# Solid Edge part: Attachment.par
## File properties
Username: m_hel
Author: m_hel
Template: Iso Metric Part.par
Last saved by: m_hel
Revision: 8
Application: Solid Edge
Accuracy: 0,990
Material: Chrome
Face Style: Chrome
Fill Style: Normal
Virtual Style: Normal
Grouping: Uncategorized
LibraryName: Custom Materials
Coef. of Thermal Exp: 0.0
Thermal Conductivity: 0.0
Specific Heat: 0.0
Modulus of Elasticity: 0.0
Poisson's Ratio: 0.0
Yield Stress: 0.0
Ultimate Stress: 0.0
Elongation: 0.0
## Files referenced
..\..\Redfisher18.asm
G:\OneDriveTemp\OneDrive\Dokumendid\TLÜ tööd\3D Modelleerimine\3d modelling\veesõiduk\Hull.par
iduk\Hull.par
iduk\Redfisher18.asm
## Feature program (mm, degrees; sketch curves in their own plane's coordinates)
sketch for "unnamed Protrusion 1" plane through (0, 0, 0) normal (0, -1, 0) x-axis (1, 0, 0)
  line (-95, -150) -> (95, -150)
  arc centre (95, -120) radius 30 from (95, -150) to (125, -120) ccw
  line (125, -120) -> (125, 50)
  line (125, 50) -> (-125, 50)
  line (-125, 50) -> (-125, -120)
  arc centre (-95, -120) radius 30 from (-95, -150) to (-125, -120) cw
  dimension (linear) = 125
  dimension (linear) = 95
extrude "unnamed Protrusion 1" add finite 20 along +normal
sketch for "ExtrudedProtrusion_2" plane through (0, 0, -50) normal (0, 1, 0) x-axis (-1, 0, 0)
  line (-125, 50) -> (125, 50)
  line (125, 100) -> (125, 50)
  line (-125, 100) -> (125, 100)
  line (-125, 50) -> (-125, 100)
extrude "ExtrudedProtrusion_2" add finite 10 along +normal
body pattern "unnamed BodyPattern 1"
pattern "unnamed Pattern 1"
sketch for "ExtrudedProtrusion_3" plane through (-125, 10, -35) normal (-1, 0, 0) x-axis (0, -1, 0)
  circle centre (0, 85) radius 30
extrude "ExtrudedProtrusion_3" add finite 250 along -normal
sketch for "unnamed Cutout 1" plane through (-125, 10, -20) normal (-1, 0, 0) x-axis (0, 0, 1)
  circle centre (70, 0) radius 15
extrude "unnamed Cutout 1" cut through along -normal
sketch for "unnamed Cutout 2" #1 plane through (0, 40, -50) normal (0, 1, 0) x-axis (-1, 0, 0)
  line (-82.5, 70) -> (-42.5, 70)
  line (-42.5, 70) -> (-42.5, 130)
  line (-42.5, 130) -> (-82.5, 130)
  line (-82.5, 130) -> (-82.5, 70)
  dimension (linear) = 42.5
  dimension (linear) = 42.5
sketch for "unnamed Cutout 2" #2 plane through (0, 40, -50) normal (0, 1, 0) x-axis (-1, 0, 0)
  line (82.5, 70) -> (42.5, 70)
  line (42.5, 70) -> (42.5, 130)
  line (42.5, 130) -> (82.5, 130)
  line (82.5, 130) -> (82.5, 70)
extrude "unnamed Cutout 2" cut through along -normal
fillet "Round_1" radius 5
sketch for "Hole_1" plane through (0, 40, -50) normal (0, 1, 0) x-axis (-1, 0, 0)
hole "Hole_1" diameter 20 through
pattern "unnamed Pattern 2" of "Hole_1"
hole "unnamed Hole 1" through
hole "unnamed Hole 2" through
hole "unnamed Hole 3" through
hole "unnamed Hole 4" through
hole "unnamed Hole 5" through
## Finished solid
Body 1: solid body, 49 faces, 118 edges, 56 vertices.
  Faces by surface: cylinder 30, plane 15, torus 4
  Edges by curve: circle 64, line 54
Bounding box of the edges (mm; curved faces can reach further): 250.000 x 60.000 x 230.000, from (-125, -20, -150) to (125, 40, 80).
Cylindrical faces by radius (mm): R5 x8, R10 x12, R15 x3, R30 x7
Toroidal faces (ring radius, tube radius in mm): R25 r5 x4
Planar faces by outward normal: +x 3, +y 2, +z 2, -x 3, -y 2, -z 3
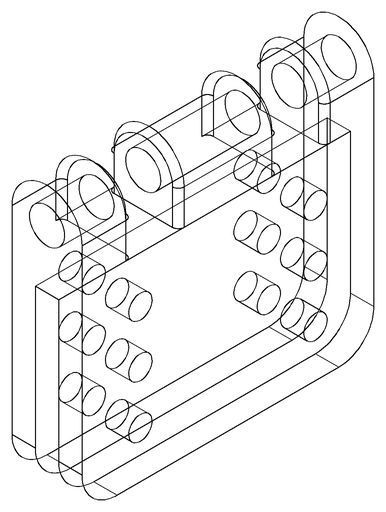
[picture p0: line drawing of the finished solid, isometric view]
